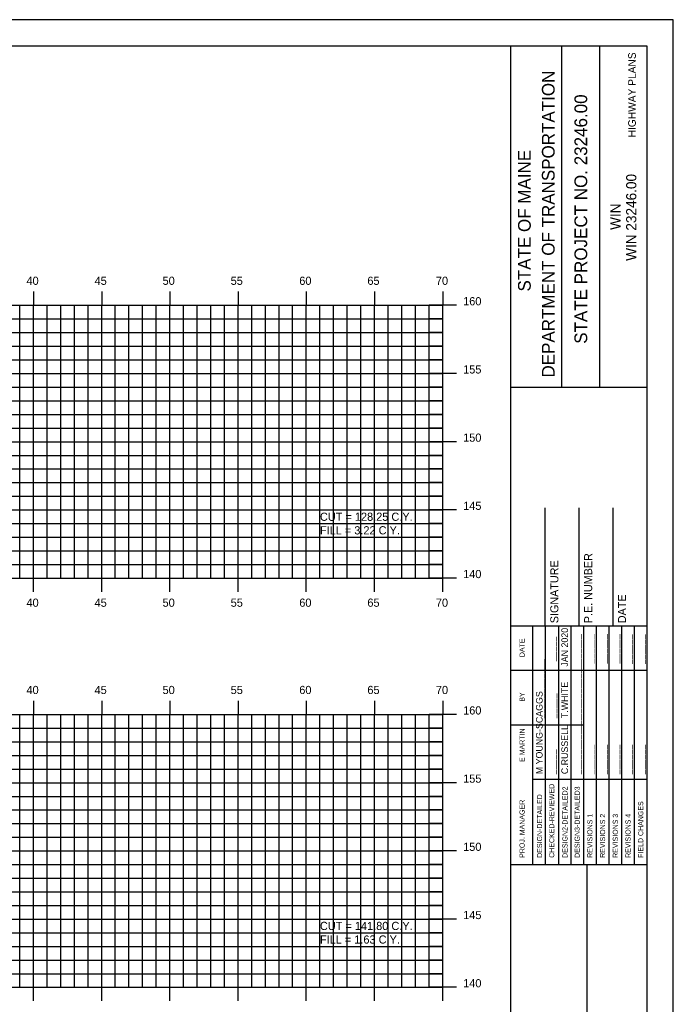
# Model space of a CAD drawing. Extents: x 1147412 to 1147582, y 608981 to 609091.
# Drawn here: x 1147533.7 to 1147581.6, y 609019.1 to 609091.3 of the extents above; entities that cross this region are included whole.
import ezdxf

# ---------------------------------------------------------------- set-up
doc = ezdxf.new("R2010")
doc.units = 0
for name, color, linetype in [('BORDER', 7, 'Continuous'), ('D_Text_Standard', 7, 'Continuous'), ('H_V ANNOTATION', 7, 'Continuous'), ('HIGHWAY_TITLE', 7, 'Continuous'), ('MAJOR', 7, 'Continuous'), ('MINOR', 7, 'Continuous'), ('PLOT BOUNDARY', 7, 'Continuous')]:
    doc.layers.add(name, color=color, linetype=linetype)

msp = doc.modelspace()

# ---------------------------------------------------------------- linework, layer by layer
at = {"layer": 'BORDER'}
for p, q in [((1147569.698, 608984.335), (1147569.698, 609089.335)), ((1147573.426, 609064.332), (1147573.426, 609089.332)), ((1147576.221, 609064.332), (1147576.221, 609089.332)), ((1147569.699, 609064.329), (1147579.698, 609064.329)), ((1147572.198, 609046.838), (1147572.198, 609055.485)), ((1147574.698, 609046.838), (1147574.698, 609055.485)), ((1147577.198, 609046.838), (1147577.198, 609055.485)), ((1147569.698, 609046.838), (1147579.698, 609046.838)), ((1147569.698, 609029.338), (1147579.698, 609029.338)), ((1147575.289, 608994.338), (1147575.289, 609029.338))]:
    msp.add_line(p, q, dxfattribs=at)
msp.add_lwpolyline([(1147419.698, 608984.335), (1147579.698, 608984.335), (1147579.698, 609089.335), (1147419.698, 609089.335)], close=True, dxfattribs=at)
for points in [[(1147571.312, 609043.588), (1147571.312, 609046.838)], [(1147572.245, 609029.341), (1147572.245, 609046.838)], [(1147573.177, 609046.838), (1147573.177, 609029.341)], [(1147574.108, 609029.341), (1147574.108, 609046.838)], [(1147575.04, 609029.341), (1147575.04, 609046.838)], [(1147575.972, 609029.341), (1147575.972, 609046.838)], [(1147576.904, 609029.341), (1147576.904, 609046.838)], [(1147577.835, 609029.341), (1147577.835, 609046.838)], [(1147578.767, 609029.341), (1147578.767, 609046.838)], [(1147571.313, 609029.341), (1147571.313, 609046.132)], [(1147569.698, 609043.588), (1147579.698, 609043.588)], [(1147569.698, 609039.588), (1147571.313, 609039.588)], [(1147571.312, 609039.588), (1147575.039, 609039.588)], [(1147571.312, 609035.588), (1147579.698, 609035.588)]]:
    msp.add_lwpolyline(points, dxfattribs=at)
at = {"layer": 'MAJOR'}
for p, q in [((1147534.697, 609071.337), (1147534.697, 609070.335)), ((1147539.697, 609071.337), (1147539.697, 609070.335)), ((1147544.697, 609071.337), (1147544.697, 609070.335)), ((1147549.697, 609071.337), (1147549.697, 609070.335)), ((1147554.697, 609071.337), (1147554.697, 609070.335)), ((1147559.697, 609071.337), (1147559.697, 609070.335)), ((1147564.697, 609071.337), (1147564.697, 609070.335)), ((1147424.697, 609070.335), (1147564.697, 609070.335)), ((1147424.697, 609070.335), (1147564.697, 609070.335)), ((1147534.697, 609050.335), (1147534.697, 609070.335)), ((1147539.697, 609050.335), (1147539.697, 609070.335)), ((1147544.697, 609050.335), (1147544.697, 609070.335)), ((1147549.697, 609050.335), (1147549.697, 609070.335)), ((1147554.697, 609050.335), (1147554.697, 609070.335)), ((1147559.697, 609050.335), (1147559.697, 609070.335)), ((1147565.699, 609070.335), (1147563.695, 609070.335)), ((1147564.697, 609050.335), (1147564.697, 609070.335)), ((1147564.697, 609050.335), (1147564.697, 609070.335)), ((1147424.697, 609065.335), (1147564.697, 609065.335)), ((1147565.699, 609065.335), (1147563.695, 609065.335)), ((1147424.697, 609060.335), (1147564.697, 609060.335)), ((1147565.699, 609060.335), (1147563.695, 609060.335)), ((1147424.697, 609055.335), (1147564.697, 609055.335)), ((1147565.699, 609055.335), (1147563.695, 609055.335)), ((1147424.697, 609050.335), (1147564.697, 609050.335)), ((1147424.697, 609050.335), (1147564.697, 609050.335)), ((1147534.697, 609049.333), (1147534.697, 609050.335)), ((1147539.697, 609049.333), (1147539.697, 609050.335)), ((1147544.697, 609049.333), (1147544.697, 609050.335)), ((1147549.697, 609049.333), (1147549.697, 609050.335)), ((1147554.697, 609049.333), (1147554.697, 609050.335)), ((1147559.697, 609049.333), (1147559.697, 609050.335)), ((1147565.699, 609050.335), (1147563.695, 609050.335)), ((1147564.697, 609049.333), (1147564.697, 609050.335)), ((1147534.697, 609041.337), (1147534.697, 609040.335)), ((1147539.697, 609041.337), (1147539.697, 609040.335)), ((1147544.697, 609041.337), (1147544.697, 609040.335)), ((1147549.697, 609041.337), (1147549.697, 609040.335)), ((1147554.697, 609041.337), (1147554.697, 609040.335)), ((1147559.697, 609041.337), (1147559.697, 609040.335)), ((1147564.697, 609041.337), (1147564.697, 609040.335)), ((1147424.697, 609040.335), (1147564.697, 609040.335)), ((1147424.697, 609040.335), (1147564.697, 609040.335)), ((1147534.697, 609020.335), (1147534.697, 609040.335)), ((1147539.697, 609020.335), (1147539.697, 609040.335)), ((1147544.697, 609020.335), (1147544.697, 609040.335)), ((1147549.697, 609020.335), (1147549.697, 609040.335)), ((1147554.697, 609020.335), (1147554.697, 609040.335)), ((1147559.697, 609020.335), (1147559.697, 609040.335)), ((1147565.699, 609040.335), (1147563.695, 609040.335)), ((1147564.697, 609020.335), (1147564.697, 609040.335)), ((1147564.697, 609020.335), (1147564.697, 609040.335)), ((1147424.697, 609035.335), (1147564.697, 609035.335)), ((1147565.699, 609035.335), (1147563.695, 609035.335)), ((1147424.697, 609030.335), (1147564.697, 609030.335)), ((1147565.699, 609030.335), (1147563.695, 609030.335)), ((1147424.697, 609025.335), (1147564.697, 609025.335)), ((1147565.699, 609025.335), (1147563.695, 609025.335)), ((1147424.697, 609020.335), (1147564.697, 609020.335)), ((1147424.697, 609020.335), (1147564.697, 609020.335)), ((1147534.697, 609019.333), (1147534.697, 609020.335)), ((1147539.697, 609019.333), (1147539.697, 609020.335)), ((1147544.697, 609019.333), (1147544.697, 609020.335)), ((1147549.697, 609019.333), (1147549.697, 609020.335)), ((1147554.697, 609019.333), (1147554.697, 609020.335)), ((1147559.697, 609019.333), (1147559.697, 609020.335)), ((1147565.699, 609020.335), (1147563.695, 609020.335)), ((1147564.697, 609019.333), (1147564.697, 609020.335))]:
    msp.add_line(p, q, dxfattribs=at)
at = {"layer": 'MINOR'}
for p, q in [((1147533.697, 609050.335), (1147533.697, 609070.335)), ((1147535.697, 609050.335), (1147535.697, 609070.335)), ((1147536.697, 609050.335), (1147536.697, 609070.335)), ((1147537.697, 609050.335), (1147537.697, 609070.335)), ((1147538.697, 609050.335), (1147538.697, 609070.335)), ((1147540.697, 609050.335), (1147540.697, 609070.335)), ((1147541.697, 609050.335), (1147541.697, 609070.335)), ((1147542.697, 609050.335), (1147542.697, 609070.335)), ((1147543.697, 609050.335), (1147543.697, 609070.335)), ((1147545.697, 609050.335), (1147545.697, 609070.335)), ((1147546.697, 609050.335), (1147546.697, 609070.335)), ((1147547.697, 609050.335), (1147547.697, 609070.335)), ((1147548.697, 609050.335), (1147548.697, 609070.335)), ((1147550.697, 609050.335), (1147550.697, 609070.335)), ((1147551.697, 609050.335), (1147551.697, 609070.335)), ((1147552.697, 609050.335), (1147552.697, 609070.335)), ((1147553.697, 609050.335), (1147553.697, 609070.335)), ((1147555.697, 609050.335), (1147555.697, 609070.335)), ((1147556.697, 609050.335), (1147556.697, 609070.335)), ((1147557.697, 609050.335), (1147557.697, 609070.335)), ((1147558.697, 609050.335), (1147558.697, 609070.335)), ((1147560.697, 609050.335), (1147560.697, 609070.335)), ((1147561.697, 609050.335), (1147561.697, 609070.335)), ((1147562.697, 609050.335), (1147562.697, 609070.335)), ((1147563.697, 609050.335), (1147563.697, 609070.335)), ((1147424.697, 609069.335), (1147564.697, 609069.335)), ((1147564.697, 609069.335), (1147563.695, 609069.335)), ((1147424.697, 609068.335), (1147564.697, 609068.335)), ((1147564.697, 609068.335), (1147563.695, 609068.335)), ((1147424.697, 609067.335), (1147564.697, 609067.335)), ((1147564.697, 609067.335), (1147563.695, 609067.335)), ((1147424.697, 609066.335), (1147564.697, 609066.335)), ((1147564.697, 609066.335), (1147563.695, 609066.335)), ((1147424.697, 609064.335), (1147564.697, 609064.335)), ((1147564.697, 609064.335), (1147563.695, 609064.335)), ((1147424.697, 609063.335), (1147564.697, 609063.335)), ((1147564.697, 609063.335), (1147563.695, 609063.335)), ((1147424.697, 609062.335), (1147564.697, 609062.335)), ((1147564.697, 609062.335), (1147563.695, 609062.335)), ((1147424.697, 609061.335), (1147564.697, 609061.335)), ((1147564.697, 609061.335), (1147563.695, 609061.335)), ((1147424.697, 609059.335), (1147564.697, 609059.335)), ((1147564.697, 609059.335), (1147563.695, 609059.335)), ((1147424.697, 609058.335), (1147564.697, 609058.335)), ((1147564.697, 609058.335), (1147563.695, 609058.335)), ((1147424.697, 609057.335), (1147564.697, 609057.335)), ((1147564.697, 609057.335), (1147563.695, 609057.335)), ((1147424.697, 609056.335), (1147564.697, 609056.335)), ((1147564.697, 609056.335), (1147563.695, 609056.335)), ((1147424.697, 609054.335), (1147564.697, 609054.335)), ((1147564.697, 609054.335), (1147563.695, 609054.335)), ((1147424.697, 609053.335), (1147564.697, 609053.335)), ((1147564.697, 609053.335), (1147563.695, 609053.335)), ((1147424.697, 609052.335), (1147564.697, 609052.335)), ((1147564.697, 609052.335), (1147563.695, 609052.335)), ((1147424.697, 609051.335), (1147564.697, 609051.335)), ((1147564.697, 609051.335), (1147563.695, 609051.335)), ((1147533.697, 609020.335), (1147533.697, 609040.335)), ((1147535.697, 609020.335), (1147535.697, 609040.335)), ((1147536.697, 609020.335), (1147536.697, 609040.335)), ((1147537.697, 609020.335), (1147537.697, 609040.335)), ((1147538.697, 609020.335), (1147538.697, 609040.335)), ((1147540.697, 609020.335), (1147540.697, 609040.335)), ((1147541.697, 609020.335), (1147541.697, 609040.335)), ((1147542.697, 609020.335), (1147542.697, 609040.335)), ((1147543.697, 609020.335), (1147543.697, 609040.335)), ((1147545.697, 609020.335), (1147545.697, 609040.335)), ((1147546.697, 609020.335), (1147546.697, 609040.335)), ((1147547.697, 609020.335), (1147547.697, 609040.335)), ((1147548.697, 609020.335), (1147548.697, 609040.335)), ((1147550.697, 609020.335), (1147550.697, 609040.335)), ((1147551.697, 609020.335), (1147551.697, 609040.335)), ((1147552.697, 609020.335), (1147552.697, 609040.335)), ((1147553.697, 609020.335), (1147553.697, 609040.335)), ((1147555.697, 609020.335), (1147555.697, 609040.335)), ((1147556.697, 609020.335), (1147556.697, 609040.335)), ((1147557.697, 609020.335), (1147557.697, 609040.335)), ((1147558.697, 609020.335), (1147558.697, 609040.335)), ((1147560.697, 609020.335), (1147560.697, 609040.335)), ((1147561.697, 609020.335), (1147561.697, 609040.335)), ((1147562.697, 609020.335), (1147562.697, 609040.335)), ((1147563.697, 609020.335), (1147563.697, 609040.335)), ((1147424.697, 609039.335), (1147564.697, 609039.335)), ((1147564.697, 609039.335), (1147563.695, 609039.335)), ((1147424.697, 609038.335), (1147564.697, 609038.335)), ((1147564.697, 609038.335), (1147563.695, 609038.335)), ((1147424.697, 609037.335), (1147564.697, 609037.335)), ((1147564.697, 609037.335), (1147563.695, 609037.335)), ((1147424.697, 609036.335), (1147564.697, 609036.335)), ((1147564.697, 609036.335), (1147563.695, 609036.335)), ((1147424.697, 609034.335), (1147564.697, 609034.335)), ((1147564.697, 609034.335), (1147563.695, 609034.335)), ((1147424.697, 609033.335), (1147564.697, 609033.335)), ((1147564.697, 609033.335), (1147563.695, 609033.335)), ((1147424.697, 609032.335), (1147564.697, 609032.335)), ((1147564.697, 609032.335), (1147563.695, 609032.335)), ((1147424.697, 609031.335), (1147564.697, 609031.335)), ((1147564.697, 609031.335), (1147563.695, 609031.335)), ((1147424.697, 609029.335), (1147564.697, 609029.335)), ((1147564.697, 609029.335), (1147563.695, 609029.335)), ((1147424.697, 609028.335), (1147564.697, 609028.335)), ((1147564.697, 609028.335), (1147563.695, 609028.335)), ((1147424.697, 609027.335), (1147564.697, 609027.335)), ((1147564.697, 609027.335), (1147563.695, 609027.335)), ((1147424.697, 609026.335), (1147564.697, 609026.335)), ((1147564.697, 609026.335), (1147563.695, 609026.335)), ((1147424.697, 609024.335), (1147564.697, 609024.335)), ((1147564.697, 609024.335), (1147563.695, 609024.335)), ((1147424.697, 609023.335), (1147564.697, 609023.335)), ((1147564.697, 609023.335), (1147563.695, 609023.335)), ((1147424.697, 609022.335), (1147564.697, 609022.335)), ((1147564.697, 609022.335), (1147563.695, 609022.335)), ((1147424.697, 609021.335), (1147564.697, 609021.335)), ((1147564.697, 609021.335), (1147563.695, 609021.335))]:
    msp.add_line(p, q, dxfattribs=at)
at = {"layer": 'PLOT BOUNDARY'}
msp.add_lwpolyline([(1147411.604, 608981.276), (1147581.604, 608981.276), (1147581.604, 609091.276), (1147411.604, 609091.276)], close=True, dxfattribs=at)

# ---------------------------------------------------------------- texts
at = {"layer": 'BORDER'}
for s, height, p in [('DEPARTMENT OF TRANSPORTATION', 0.93176, (1147572.904, 609065.041)), ('STATE PROJECT NO. 23246.00', 0.93176, (1147575.29, 609067.517)), ('STATE OF MAINE', 0.93176, (1147571.153, 609071.347)), ('WIN 23246.00', 0.74527, (1147578.893, 609073.596)), ('WIN', 0.7453, (1147577.734, 609075.865)), ('SIGNATURE', 0.5906, (1147573.178, 609047.03)), ('P.E. NUMBER', 0.59055, (1147575.658, 609047.03)), ('DATE', 0.5906, (1147578.139, 609047.03)), ('JAN 2020', 0.4845, (1147573.884, 609043.843)), ('DATE', 0.3714, (1147570.702, 609044.544)), ('_____', 0.4845, (1147572.915, 609044.243)), ('______', 0.4845, (1147574.778, 609044.063)), ('______', 0.4845, (1147575.71, 609044.065)), ('______', 0.4845, (1147576.642, 609044.067)), ('______', 0.4845, (1147577.573, 609044.067)), ('______', 0.4845, (1147578.505, 609044.036)), ('______', 0.4845, (1147579.437, 609044.036)), ('____________', 0.48455, (1147572.021, 609040.073)), ('____________', 0.48455, (1147574.778, 609040.073)), ('T.WHITE', 0.4845, (1147573.884, 609040.073)), ('BY', 0.3714, (1147570.702, 609041.273)), ('M YOUNG-SCAGGS', 0.48455, (1147572.021, 609035.961)), ('_____', 0.4845, (1147572.952, 609040.073)), ('____________', 0.48455, (1147574.778, 609035.961)), ('C.RUSSELL', 0.4845, (1147573.884, 609035.961)), ('E MARTIN', 0.3727, (1147570.702, 609036.855)), ('_____', 0.4845, (1147572.915, 609035.961)), ('______', 0.4845, (1147575.71, 609035.961)), ('______', 0.4845, (1147576.642, 609035.961)), ('______', 0.4845, (1147577.573, 609035.961)), ('______', 0.4845, (1147578.505, 609035.961)), ('______', 0.4845, (1147579.437, 609035.961)), ('CHECKED-REVIEWED', 0.37275, (1147572.879, 609029.826)), ('DESIGN2-DETAILED2', 0.37275, (1147573.848, 609029.826)), ('DESIGN3-DETAILED3', 0.37275, (1147574.742, 609029.826)), ('DESIGN-DETAILED', 0.37275, (1147571.984, 609029.826)), ('PROJ. MANAGER', 0.37275, (1147570.702, 609029.826)), ('FIELD CHANGES', 0.37275, (1147579.4, 609029.826)), ('REVISIONS 1', 0.37275, (1147575.674, 609029.826)), ('REVISIONS 2', 0.37275, (1147576.605, 609029.826)), ('REVISIONS 3', 0.37275, (1147577.537, 609029.826)), ('REVISIONS 4', 0.37275, (1147578.469, 609029.826))]:
    msp.add_text(s, height=height, rotation=90, dxfattribs=at).set_placement(p)
at = {"layer": 'D_Text_Standard'}
for s, p in [('CUT = 128.25 C.Y.', (1147555.697, 609054.535)), ('FILL = 3.22 C.Y.', (1147555.697, 609053.539)), ('CUT = 141.80 C.Y.', (1147555.697, 609024.535)), ('FILL = 1.63 C.Y.', (1147555.697, 609023.539))]:
    msp.add_text(s, height=0.6, dxfattribs=at).set_placement(p)
at = {"layer": 'H_V ANNOTATION'}
for s, p in [('40', (1147534.184, 609071.835)), ('45', (1147539.176, 609071.835)), ('50', (1147544.162, 609071.835)), ('55', (1147549.154, 609071.835)), ('60', (1147554.184, 609071.835)), ('65', (1147559.176, 609071.835)), ('70', (1147564.2, 609071.835)), ('160', (1147566.197, 609070.335)), ('155', (1147566.197, 609065.335)), ('150', (1147566.197, 609060.335)), ('145', (1147566.197, 609055.335)), ('140', (1147566.197, 609050.335)), ('40', (1147534.184, 609048.235)), ('45', (1147539.176, 609048.235)), ('50', (1147544.162, 609048.235)), ('55', (1147549.154, 609048.235)), ('60', (1147554.184, 609048.235)), ('65', (1147559.176, 609048.235)), ('70', (1147564.2, 609048.235)), ('40', (1147534.184, 609041.835)), ('45', (1147539.176, 609041.835)), ('50', (1147544.162, 609041.835)), ('55', (1147549.154, 609041.835)), ('60', (1147554.184, 609041.835)), ('65', (1147559.176, 609041.835)), ('70', (1147564.2, 609041.835)), ('160', (1147566.197, 609040.335)), ('155', (1147566.197, 609035.335)), ('150', (1147566.197, 609030.335)), ('145', (1147566.197, 609025.335)), ('140', (1147566.197, 609020.335))]:
    msp.add_text(s, height=0.6, dxfattribs=at).set_placement(p)
at = {"layer": 'HIGHWAY_TITLE'}
msp.add_text('HIGHWAY PLANS', height=0.55901, rotation=90, dxfattribs=at).set_placement((1147578.856, 609082.65))

doc.saveas('drawing.dxf')
